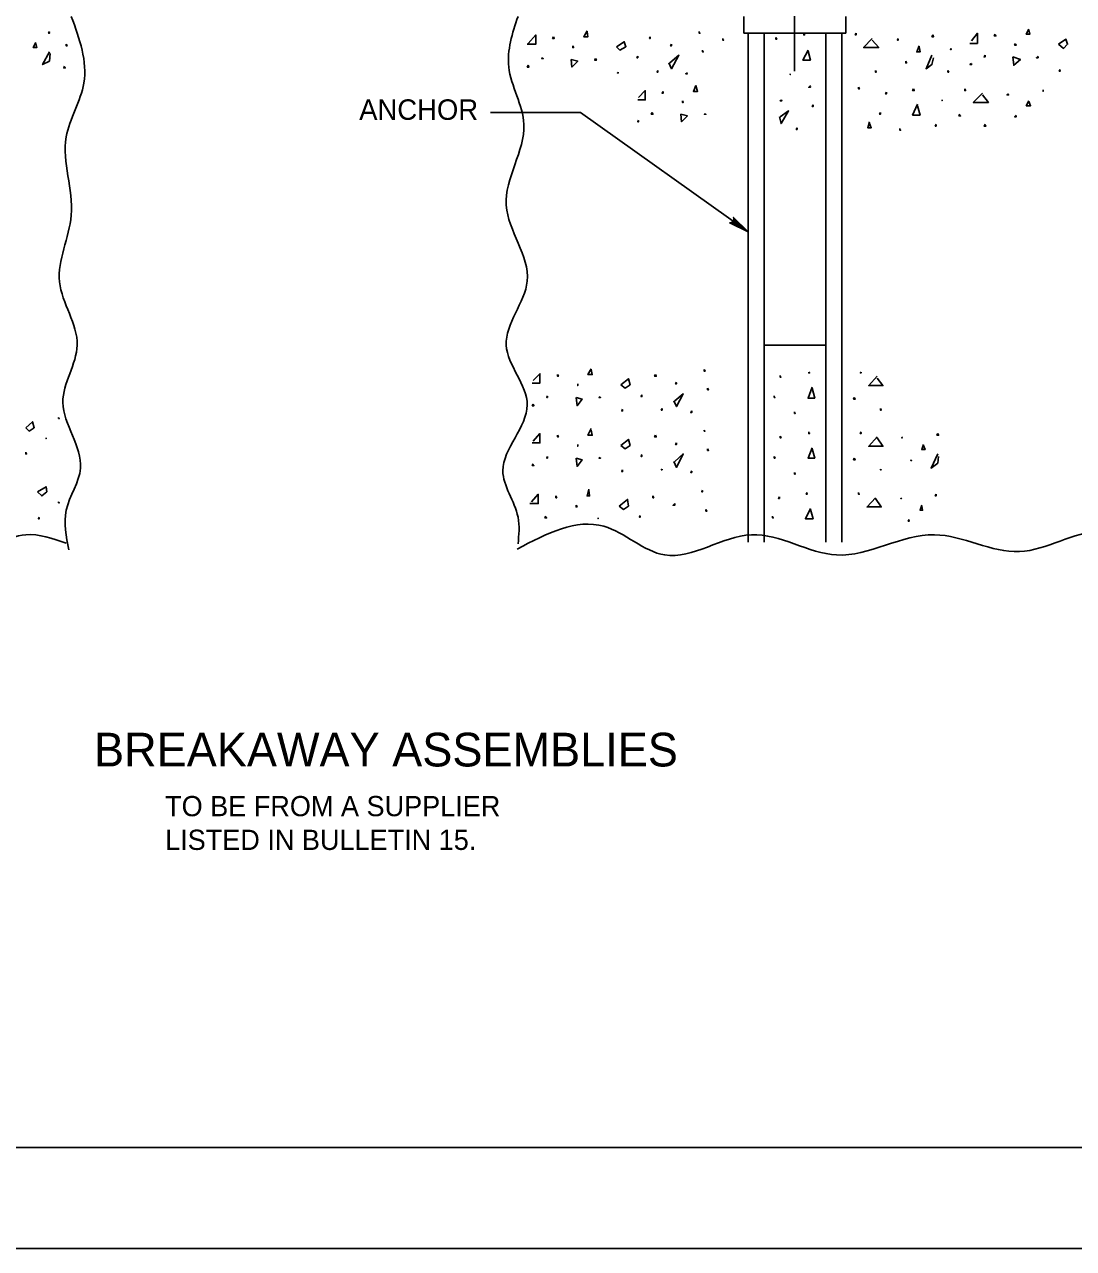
# Model space of a CAD drawing. Extents: x 637580 to 641008, y 294594 to 295782.
# Drawn here: x 637787.5 to 637943.1, y 294593.6 to 294775.2 of the extents above; entities that cross this region are included whole.
import ezdxf

# ---------------------------------------------------------------- set-up
doc = ezdxf.new("R2010")
doc.units = 0
for name, color, linetype in [('1', 7, 'Continuous'), ('2', 7, 'Continuous'), ('3', 7, 'Continuous'), ('PLT-BNDY', 7, 'Continuous')]:
    doc.layers.add(name, color=color, linetype=linetype)

# ---------------------------------------------------------------- blocks, each defined once
blk = doc.blocks.new('RARROW')
at = {"layer": '3'}
blk.add_lwpolyline([(-2.2695, 0.285), (-2.184875, 0.12075), (0, 0), (-2.2695, 0.285), (-2.38575, 0.384625), (0, 0), (-2.183125, -0.108), (-2.262875, -0.2705), (0, 0), (-2.38575, -0.379125), (-2.262875, -0.2705)], dxfattribs=at)

msp = doc.modelspace()

# ---------------------------------------------------------------- linework, layer by layer
at = {"layer": '1'}
for p, q in [((638406.31, 294608.63), (637620.31, 294608.63)), ((637620.31, 294608.63), (638206.31, 294608.63))]:
    msp.add_line(p, q, dxfattribs=at)
at = {"layer": '2'}
for p, q in [((637901.68, 294768.25), (637901.68, 294836)), ((637894.18, 294776.38), (637894.18, 294773.88)), ((637909.3, 294773.88), (637909.3, 294776.38)), ((637909.3, 294773.88), (637894.18, 294773.88)), ((637894.8, 294773.88), (637894.8, 294698.38)), ((637897.18, 294773.88), (637897.18, 294698.38)), ((637906.3, 294698.38), (637906.3, 294773.88)), ((637908.68, 294698.38), (637908.68, 294773.88)), ((637869.93, 294762.13), (637856.6, 294762.13)), ((637894.8, 294744.41), (637869.93, 294762.13)), ((637906.3, 294727.63), (637897.18, 294727.63))]:
    msp.add_line(p, q, dxfattribs=at)
for points in [[(637791.19, 294774.13), (637791.06, 294773.88), (637791.19, 294773.88), (637791.19, 294774)], [(637870.93, 294774.25), (637870.43, 294773.38), (637871.05, 294773.38), (637870.93, 294774.13)], [(637887.55, 294774.13), (637887.55, 294773.88), (637887.68, 294773.88), (637887.55, 294774)], [(637936.43, 294774.5), (637936.05, 294773.75), (637936.55, 294773.75), (637936.43, 294774.38)], [(637789.19, 294772.5), (637788.81, 294771.75), (637789.31, 294771.75), (637789.19, 294772.38)], [(637793.69, 294772.25), (637793.69, 294772), (637793.81, 294772), (637793.69, 294772.25)], [(637862.18, 294772.38), (637863.3, 294773.63), (637863.3, 294772.25), (637862.05, 294772.25)], [(637865.93, 294773.38), (637865.8, 294773.13), (637866.05, 294773.13), (637865.93, 294773.38)], [(637875.3, 294771.88), (637876.43, 294772.63), (637876.68, 294771.88), (637875.8, 294771.38), (637875.3, 294771.88)], [(637880.3, 294773.38), (637880.18, 294773.13), (637880.3, 294773.13), (637880.3, 294773.38)], [(637883.43, 294772.25), (637883.3, 294772), (637883.43, 294772), (637883.43, 294772.25)], [(637891.05, 294773.13), (637891.05, 294772.88), (637891.18, 294772.88), (637891.05, 294773)], [(637898.93, 294773.25), (637898.93, 294773), (637899.05, 294773), (637898.93, 294773.25)], [(637903.05, 294773.88), (637903.05, 294773.63), (637903.18, 294773.63), (637903.05, 294773.88)], [(637910.8, 294773.88), (637910.68, 294773.63), (637910.8, 294773.63), (637910.8, 294773.88)], [(637913.18, 294773.13), (637911.93, 294771.75), (637914.18, 294771.75), (637913.18, 294772.88)], [(637917.05, 294773.13), (637916.93, 294772.88), (637917.05, 294772.88), (637917.05, 294773)], [(637922.18, 294773.63), (637922.05, 294773.38), (637922.3, 294773.38), (637922.18, 294773.63)], [(637927.93, 294772.75), (637928.8, 294773.88), (637928.8, 294772.38), (637927.68, 294772.38)], [(637931.43, 294773.75), (637931.3, 294773.5), (637931.55, 294773.5), (637931.43, 294773.63)], [(637934.43, 294772.38), (637934.3, 294772.13), (637934.55, 294772.13), (637934.43, 294772.25)], [(637940.8, 294772.25), (637941.93, 294773), (637942.18, 294772.25), (637941.55, 294771.63), (637940.8, 294772.25)], [(637791.19, 294771.13), (637790.19, 294769.25), (637791.19, 294769.75), (637791.31, 294770.88)], [(637868.8, 294772), (637868.8, 294771.75), (637868.93, 294771.75), (637868.8, 294772)], [(637878.43, 294770.5), (637878.3, 294770.25), (637878.43, 294770.25), (637878.43, 294770.5)], [(637883.18, 294769.5), (637884.55, 294770.63), (637883.43, 294768.63), (637883.05, 294769.5)], [(637888.05, 294771.38), (637888.05, 294771.13), (637888.18, 294771.13), (637888.05, 294771.25)], [(637903.68, 294771.38), (637902.93, 294769.88), (637904.05, 294769.88), (637903.68, 294771.25)], [(637920.18, 294772), (637919.8, 294771.13), (637920.3, 294771.13), (637920.18, 294771.88)], [(637922.05, 294770.63), (637921.18, 294768.63), (637922.05, 294769.25), (637922.3, 294770.25)], [(637924.93, 294771.63), (637924.8, 294771.5), (637924.93, 294771.5), (637924.93, 294771.63)], [(637929.93, 294770.63), (637929.8, 294770.38), (637929.93, 294770.38), (637929.93, 294770.63)], [(637934.05, 294770.38), (637934.18, 294769.13), (637935.18, 294770), (637934.05, 294770.38)], [(637937.8, 294770.5), (637937.55, 294770.25), (637937.8, 294770.25), (637937.8, 294770.38)], [(637793.44, 294769), (637793.31, 294768.75), (637793.56, 294768.75), (637793.44, 294768.88)], [(637862.18, 294769.13), (637862.05, 294768.88), (637862.3, 294768.88), (637862.18, 294769.13)], [(637864.3, 294770.25), (637864.18, 294770.13), (637864.43, 294770.13), (637864.3, 294770.25)], [(637868.55, 294770), (637868.68, 294768.88), (637869.55, 294769.75), (637868.55, 294770)], [(637872.18, 294770.13), (637872.05, 294769.88), (637872.3, 294769.88), (637872.18, 294770.13)], [(637918.18, 294769.75), (637918.18, 294769.5), (637918.3, 294769.5), (637918.18, 294769.75)], [(637927.93, 294769.38), (637927.68, 294769.25), (637927.93, 294769.25), (637927.93, 294769.38)], [(637875.55, 294768.13), (637875.43, 294768), (637875.55, 294768), (637875.55, 294768.13)], [(637881.43, 294768.38), (637881.3, 294768.13), (637881.43, 294768.13), (637881.43, 294768.38)], [(637885.8, 294768), (637885.55, 294767.88), (637885.8, 294767.88), (637885.8, 294767.88)], [(637901.05, 294767.88), (637901.05, 294767.75), (637901.05, 294767.75), (637901.05, 294767.88)], [(637913.68, 294768.38), (637913.68, 294768.13), (637913.8, 294768.13), (637913.68, 294768.38)], [(637924.43, 294768.38), (637924.43, 294768.13), (637924.55, 294768.13), (637924.43, 294768.38)], [(637941.05, 294768.5), (637940.93, 294768.25), (637941.05, 294768.25), (637941.05, 294768.38)], [(637878.55, 294764.38), (637879.55, 294765.38), (637879.55, 294764), (637878.43, 294764)], [(637882.18, 294765.25), (637882.05, 294765), (637882.18, 294765), (637882.18, 294765.25)], [(637887.05, 294766.13), (637886.68, 294765.25), (637887.3, 294765.25), (637887.05, 294766.13)], [(637904.05, 294766.13), (637903.8, 294765.88), (637904.05, 294765.88), (637904.05, 294766)], [(637911.18, 294765.88), (637911.18, 294765.63), (637911.3, 294765.63), (637911.18, 294765.88)], [(637915.3, 294765.13), (637915.18, 294764.88), (637915.3, 294764.88), (637915.3, 294765.13)], [(637919.3, 294765.63), (637919.18, 294765.38), (637919.43, 294765.38), (637919.3, 294765.63)], [(637926.93, 294765.63), (637926.93, 294765.38), (637927.05, 294765.38), (637926.93, 294765.63)], [(637929.55, 294765), (637928.18, 294763.63), (637930.43, 294763.63), (637929.55, 294764.75)], [(637938.55, 294765.5), (637938.55, 294765.25), (637938.55, 294765.25), (637938.55, 294765.38)], [(637885.05, 294763.88), (637885.05, 294763.63), (637885.18, 294763.63), (637885.05, 294763.88)], [(637899.68, 294764), (637899.55, 294763.88), (637899.8, 294763.88), (637899.68, 294764)], [(637904.43, 294763.25), (637904.3, 294763), (637904.43, 294763), (637904.43, 294763.25)], [(637919.93, 294763.38), (637919.18, 294761.75), (637920.3, 294761.75), (637919.93, 294763.13)], [(637923.55, 294764), (637923.55, 294763.88), (637923.55, 294763.88), (637923.55, 294764)], [(637933.3, 294764.88), (637933.18, 294764.75), (637933.43, 294764.75), (637933.3, 294764.88)], [(637936.43, 294763.88), (637936.05, 294763.13), (637936.68, 294763.13), (637936.43, 294763.75)], [(637880.55, 294762.13), (637880.43, 294761.88), (637880.68, 294761.88), (637880.55, 294762.13)], [(637884.8, 294761.88), (637884.93, 294760.75), (637885.8, 294761.63), (637884.8, 294761.88)], [(637888.43, 294761.88), (637888.3, 294761.88), (637888.55, 294761.88), (637888.43, 294761.88)], [(637899.55, 294761.5), (637900.8, 294762.38), (637899.68, 294760.5), (637899.43, 294761.5)], [(637914.43, 294762.13), (637914.3, 294761.88), (637914.43, 294761.88), (637914.43, 294762.13)], [(637926.18, 294761.88), (637926.05, 294761.63), (637926.3, 294761.63), (637926.18, 294761.75)], [(637934.55, 294761.75), (637934.3, 294761.5), (637934.55, 294761.5), (637934.55, 294761.63)], [(637878.55, 294761), (637878.43, 294760.75), (637878.55, 294760.75), (637878.55, 294760.88)], [(637902.05, 294759.88), (637901.93, 294759.63), (637902.05, 294759.63), (637902.05, 294759.88)], [(637912.8, 294760.75), (637912.55, 294759.88), (637913.05, 294759.88), (637912.8, 294760.5)], [(637917.3, 294759.75), (637917.3, 294759.5), (637917.43, 294759.5), (637917.3, 294759.63)], [(637922.68, 294760.38), (637922.55, 294760.13), (637922.68, 294760.13), (637922.68, 294760.25)], [(637929.93, 294760.38), (637929.8, 294760.13), (637930.05, 294760.13), (637929.93, 294760.25)], [(637862.93, 294722.38), (637863.93, 294723.38), (637863.93, 294722), (637862.8, 294722)], [(637866.55, 294723.25), (637866.55, 294723), (637866.68, 294723), (637866.55, 294723.25)], [(637871.55, 294724.13), (637871.05, 294723.25), (637871.68, 294723.25), (637871.55, 294724)], [(637881.05, 294723.25), (637880.93, 294723), (637881.18, 294723), (637881.05, 294723.25)], [(637888.3, 294724), (637888.3, 294723.75), (637888.43, 294723.75), (637888.3, 294724)], [(637903.8, 294723.63), (637903.8, 294723.5), (637903.93, 294723.5), (637903.8, 294723.63)], [(637911.55, 294723.63), (637911.43, 294723.5), (637911.55, 294723.5), (637911.55, 294723.63)], [(637869.55, 294721.88), (637869.55, 294721.63), (637869.55, 294721.63), (637869.55, 294721.88)], [(637875.93, 294721.75), (637877.05, 294722.63), (637877.3, 294721.75), (637876.55, 294721.25), (637875.93, 294721.75)], [(637884.18, 294722.13), (637884.05, 294721.88), (637884.18, 294721.88), (637884.18, 294722)], [(637899.55, 294723.13), (637899.55, 294722.88), (637899.68, 294722.88), (637899.55, 294723)], [(637904.3, 294721.38), (637903.68, 294719.75), (637904.68, 294719.75), (637904.3, 294721.25)], [(637913.93, 294723), (637912.68, 294721.63), (637914.8, 294721.63), (637913.93, 294722.75)], [(637865.05, 294720.13), (637864.93, 294719.88), (637865.05, 294719.88), (637865.05, 294720)], [(637869.3, 294719.88), (637869.43, 294718.63), (637870.18, 294719.63), (637869.3, 294719.88)], [(637872.8, 294720), (637872.68, 294719.88), (637872.93, 294719.88), (637872.8, 294719.88)], [(637879.05, 294720.25), (637878.93, 294720), (637879.05, 294720), (637879.05, 294720.25)], [(637883.93, 294719.38), (637885.18, 294720.38), (637884.18, 294718.5), (637883.8, 294719.38)], [(637888.8, 294721.25), (637888.8, 294721), (637888.93, 294721), (637888.8, 294721.25)], [(637898.68, 294720.13), (637898.68, 294719.88), (637898.8, 294719.88), (637898.68, 294720)], [(637910.55, 294719.88), (637910.43, 294719.63), (637910.68, 294719.63), (637910.55, 294719.88)], [(637862.93, 294718.88), (637862.8, 294718.63), (637863.05, 294718.63), (637862.93, 294718.88)], [(637876.18, 294718.13), (637876.05, 294717.88), (637876.18, 294717.88), (637876.18, 294718)], [(637882.05, 294718.25), (637881.93, 294718), (637882.05, 294718), (637882.05, 294718.25)], [(637886.43, 294717.88), (637886.3, 294717.63), (637886.43, 294717.63), (637886.43, 294717.88)], [(637901.68, 294717.75), (637901.68, 294717.5), (637901.8, 294717.5), (637901.68, 294717.63)], [(637914.43, 294718.25), (637914.43, 294718), (637914.55, 294718), (637914.43, 294718.25)], [(637787.69, 294715.38), (637788.69, 294716.25), (637788.94, 294715.38), (637788.19, 294714.88), (637787.69, 294715.38)], [(637792.56, 294716.88), (637792.56, 294716.75), (637792.69, 294716.75), (637792.56, 294716.88)], [(637862.93, 294713.38), (637863.93, 294714.5), (637863.93, 294713.13), (637862.8, 294713.13)], [(637866.55, 294714.25), (637866.55, 294714), (637866.68, 294714), (637866.55, 294714.25)], [(637871.55, 294715.25), (637871.05, 294714.25), (637871.68, 294714.25), (637871.55, 294715)], [(637881.05, 294714.25), (637880.93, 294714), (637881.18, 294714), (637881.05, 294714.25)], [(637888.3, 294715), (637888.3, 294714.88), (637888.43, 294714.88), (637888.3, 294715)], [(637899.55, 294714.13), (637899.55, 294713.88), (637899.68, 294713.88), (637899.55, 294714.13)], [(637903.8, 294714.75), (637903.8, 294714.5), (637903.93, 294714.5), (637903.8, 294714.63)], [(637911.55, 294714.75), (637911.43, 294714.5), (637911.55, 294714.5), (637911.55, 294714.63)], [(637922.93, 294714.5), (637922.8, 294714.25), (637923.05, 294714.25), (637922.93, 294714.5)], [(637790.69, 294713.88), (637790.69, 294713.75), (637790.69, 294713.75), (637790.69, 294713.88)], [(637869.55, 294712.88), (637869.55, 294712.63), (637869.55, 294712.63), (637869.55, 294712.88)], [(637875.93, 294712.75), (637877.05, 294713.63), (637877.3, 294712.75), (637876.55, 294712.25), (637875.93, 294712.75)], [(637884.18, 294713.13), (637884.05, 294712.88), (637884.18, 294712.88), (637884.18, 294713.13)], [(637888.8, 294712.25), (637888.8, 294712), (637888.93, 294712), (637888.8, 294712.25)], [(637904.3, 294712.38), (637903.68, 294710.88), (637904.68, 294710.88), (637904.3, 294712.25)], [(637913.93, 294714), (637912.68, 294712.63), (637914.8, 294712.63), (637913.93, 294713.88)], [(637917.68, 294714), (637917.55, 294713.88), (637917.68, 294713.88), (637917.68, 294713.88)], [(637920.8, 294712.88), (637920.55, 294712.13), (637921.05, 294712.13), (637920.8, 294712.75)], [(637787.69, 294711.75), (637787.69, 294711.5), (637787.81, 294711.5), (637787.69, 294711.63)], [(637865.05, 294711.13), (637864.93, 294710.88), (637865.05, 294710.88), (637865.05, 294711.13)], [(637869.3, 294710.88), (637869.43, 294709.63), (637870.18, 294710.63), (637869.3, 294710.88)], [(637872.8, 294711), (637872.68, 294710.88), (637872.93, 294710.88), (637872.8, 294710.88)], [(637879.05, 294711.38), (637878.93, 294711.13), (637879.05, 294711.13), (637879.05, 294711.25)], [(637883.93, 294710.38), (637885.18, 294711.5), (637884.18, 294709.5), (637883.8, 294710.38)], [(637898.68, 294711.13), (637898.68, 294710.88), (637898.8, 294710.88), (637898.68, 294711.13)], [(637910.55, 294710.88), (637910.43, 294710.63), (637910.68, 294710.63), (637910.55, 294710.88)], [(637918.93, 294710.63), (637918.93, 294710.5), (637919.05, 294710.5), (637918.93, 294710.63)], [(637922.93, 294711.5), (637921.93, 294709.38), (637922.93, 294710.13), (637923.05, 294711.13)], [(637862.93, 294710), (637862.8, 294709.75), (637863.05, 294709.75), (637862.93, 294709.88)], [(637876.18, 294709.13), (637876.05, 294708.88), (637876.18, 294708.88), (637876.18, 294709.13)], [(637882.05, 294709.25), (637881.93, 294709.13), (637882.05, 294709.13), (637882.05, 294709.25)], [(637886.43, 294709), (637886.3, 294708.75), (637886.43, 294708.75), (637886.43, 294708.88)], [(637901.68, 294708.75), (637901.68, 294708.5), (637901.8, 294708.5), (637901.68, 294708.75)], [(637914.43, 294709.25), (637914.43, 294709.13), (637914.55, 294709.13), (637914.43, 294709.25)], [(637789.44, 294705.88), (637790.69, 294706.63), (637790.81, 294705.88), (637790.06, 294705.25), (637789.44, 294705.88)], [(637862.68, 294704.38), (637863.68, 294705.5), (637863.68, 294704.13), (637862.43, 294704.13)], [(637866.3, 294705.25), (637866.3, 294705), (637866.43, 294705), (637866.3, 294705.25)], [(637871.18, 294706.25), (637870.93, 294705.25), (637871.3, 294705.25), (637871.18, 294706.13)], [(637880.68, 294705.25), (637880.68, 294705), (637880.8, 294705), (637880.68, 294705.25)], [(637888.05, 294706.13), (637887.93, 294705.88), (637888.05, 294705.88), (637888.05, 294706)], [(637899.43, 294705.13), (637899.3, 294704.88), (637899.43, 294704.88), (637899.43, 294705.13)], [(637903.55, 294705.75), (637903.43, 294705.5), (637903.55, 294705.5), (637903.55, 294705.63)], [(637911.18, 294705.75), (637911.18, 294705.5), (637911.3, 294705.5), (637911.18, 294705.63)], [(637913.68, 294705), (637912.43, 294703.63), (637914.55, 294703.63), (637913.68, 294704.88)], [(637917.55, 294705), (637917.43, 294704.88), (637917.55, 294704.88), (637917.55, 294704.88)], [(637922.68, 294705.5), (637922.55, 294705.25), (637922.68, 294705.25), (637922.68, 294705.5)], [(637792.56, 294704.38), (637792.56, 294704.25), (637792.69, 294704.25), (637792.56, 294704.38)], [(637869.3, 294703.88), (637869.3, 294703.63), (637869.43, 294703.63), (637869.3, 294703.88)], [(637875.68, 294703.75), (637876.93, 294704.75), (637877.05, 294703.75), (637876.3, 294703.25), (637875.68, 294703.75)], [(637883.93, 294704.13), (637883.68, 294703.88), (637883.93, 294703.88), (637883.93, 294704.13)], [(637888.55, 294703.25), (637888.55, 294703), (637888.68, 294703), (637888.55, 294703.25)], [(637904.05, 294703.38), (637903.3, 294701.88), (637904.43, 294701.88), (637904.05, 294703.25)], [(637920.55, 294703.88), (637920.3, 294703.13), (637920.68, 294703.13), (637920.55, 294703.75)], [(637789.69, 294702.13), (637789.56, 294701.88), (637789.69, 294701.88), (637789.69, 294702)], [(637864.8, 294702.25), (637864.68, 294702), (637864.93, 294702), (637864.8, 294702.13)], [(637872.55, 294702), (637872.55, 294701.88), (637872.55, 294701.88), (637872.55, 294702)], [(637878.8, 294702.38), (637878.68, 294702.13), (637878.8, 294702.13), (637878.8, 294702.25)], [(637898.43, 294702.25), (637898.43, 294702), (637898.55, 294702), (637898.43, 294702.13)], [(637918.68, 294701.75), (637918.55, 294701.5), (637918.68, 294701.5), (637918.68, 294701.63)]]:
    msp.add_lwpolyline(points, dxfattribs=at)
for points in [[(637794.44, 294776.38), (637796.31, 294766.5), (637793.69, 294758.5), (637794.44, 294746.88), (637792.69, 294737), (637795.31, 294727.63), (637793.19, 294719.13), (637795.81, 294709.38), (637793.69, 294703.13), (637794.06, 294697.25)], [(637860.68, 294776.38), (637859.3, 294768.88), (637861.55, 294760.38), (637858.93, 294748.38), (637862.05, 294737.13), (637858.93, 294727.63), (637862.05, 294718.75), (637858.43, 294709), (637860.68, 294702.13), (637860.68, 294698.13)], [(637860.55, 294697.38), (637873.43, 294700.75), (637882.43, 294696.5), (637895.3, 294699.5), (637907.93, 294696.5), (637922.43, 294699.5), (637935.05, 294697), (637947.05, 294700), (637959.55, 294697), (637971.3, 294699.5), (637985.55, 294696.5), (637995.05, 294700), (638007.55, 294697), (638018.3, 294700), (638032.55, 294697), (638042.43, 294699.5), (638056.68, 294696.5), (638064.8, 294699.5), (638078.18, 294697), (638088.93, 294699.5), (638102.05, 294697), (638112.8, 294699.5), (638127.05, 294696.5), (638136.55, 294699.5), (638150.3, 294696.5), (638158.43, 294700), (638170.18, 294696.5), (638184.43, 294698.63)], [(637672.69, 294698.63), (637680.94, 294699), (637688.69, 294697), (637697.69, 294698.63), (637704.56, 294697), (637714.06, 294699), (637723.19, 294697.75), (637731.31, 294699.5), (637739.56, 294697), (637749.81, 294700), (637759.19, 294697), (637769.69, 294699), (637779.06, 294697), (637787.69, 294699.5), (637793.69, 294698.25)]]:
    msp.add_spline(points, degree=3, dxfattribs=at)
at = {"layer": 'PLT-BNDY'}
msp.add_lwpolyline([(637580.31, 295187.63), (638421.31, 295187.63), (638421.31, 294593.63), (637580.31, 294593.63)], close=True, dxfattribs=at)

# ---------------------------------------------------------------- block references
at = {"layer": '2', "xscale": 1.2574347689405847, "yscale": 1.3092961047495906, "rotation": -35.58297216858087}
msp.add_blockref('RARROW', (637894.8, 294744.41), dxfattribs=at)

# ---------------------------------------------------------------- texts
at = {"layer": '2'}
msp.add_text('BREAKAWAY ASSEMBLIES', height=5, dxfattribs=at).set_placement((637797.81, 294665.13))
at = {"layer": '3'}
for s, height, p in [('ANCHOR', 3.043, (637837.13, 294761.04)), ('TO BE FROM A SUPPLIER', 3, (637808.35, 294657.75)), ('LISTED IN BULLETIN 15.', 3, (637808.35, 294652.75))]:
    msp.add_text(s, height=height, dxfattribs=at).set_placement(p)

doc.saveas('drawing.dxf')
